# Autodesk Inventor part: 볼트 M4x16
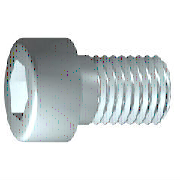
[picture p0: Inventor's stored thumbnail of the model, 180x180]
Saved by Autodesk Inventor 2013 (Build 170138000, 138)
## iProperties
IsCustomPart: 1
Created: 2012-02
Part Number: 볼트 M4x16
Material: 강철, 연강
Description: 6각머리 태핑 나사
Document SubType Name: Modeling
Standard: KS B 1003
Designer: mduedu
Standards Organization: KS
Language: ko-KR
Size Designation: M 4 x 16
Categories: <MemberInstance><Categories><Category DisplayName="조임쇠" InternalName="e4da775c-781d-43d5-af7c-5136215cf5a6" Mnemonic="FSTN"><Category DisplayName="볼트" InternalN
Density: 1 g/cm^3
Author: mduedu
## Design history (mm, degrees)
sketch "스케치1"
  geometry: L1 (-1, 0)-(16, 0); L2 (16, 0)-(16, 2); L3 (16, 2)-(1.75, 2); L4 (1.75, 2)-(1.32, 2); L5 (1.32, 2)-(0, 2); L6 (0, 2)-(0, 3.5); L7 (0, 3.5)-(-4, 3.5); L8 (-4, 3.5)-(-4, 1.732); L9 (-4, 1.732)-(-2, 1.732); L10 (-2, 1.732)-(-1, 0); L11 (-8, 0)-(20, 0) reference; L12 (0, -0.7)-(0, 4.2) reference; L13 (1.75, 2)-(0, 2)
  constraints: 22 end point, 6 parallel, 2 collinear, 2 perpendicular, 1 horizontal, 1 point on line
  dimensions: "d1" = 14.25 distance from line of L3.end L2 (= GEL); "d2" = 0.42952 distance of L4.end L3.end (computed from GAL); "d3" = 4 distance between parallel lines of L8 L6 (= KOH); "d4" = 2 distance of L8.end L9.end (= INTI); "d5" = 60 deg angle of L10 L1; "d6" = 4 diameter of L3 L1 (= GD); "d7" = 4 diameter of L5 L1 (= BDM); "d8" = 3.4641 diameter of L9 L1 (= 1.1547 x SW); "d9" = 7 diameter of L7 L1 (= KOD); "d26" = 16 distance between parallel lines of L12 L2 (= NLG)
revolve "본체" sketch "스케치1" stored, may be unused: angle "d10" = 90 deg
sketch "스케치2"
  geometry: L1 (0, -4.9)-(0, 4.9) reference; L2 (-4.9, 0)-(4.9, 0) reference; L3 (1.732, 0)-(0.866, -1.5); L4 (0.866, -1.5)-(-0.866, -1.5); L5 (-0.866, -1.5)-(-1.732, 0); L6 (-1.732, 0)-(-0.866, 1.5); L7 (-0.866, 1.5)-(0.866, 1.5); L8 (0.866, 1.5)-(1.732, 0); 2 further points
  constraints: 12 end point, 1 coincident, 1 horizontal alignment, 1 point on line, 12 other
extrude "슬롯" join sketch "스케치2" stored distance "d11" = 10; taper "d12" = 0 deg
workplane "Work Plane1"
fillet "Fillet2" dims "d30" = 0.1 (= R)
body "Solid1"
fillet "모깎기1" dims "d17" = 0.4 (= RR)
feature "스레드" dims "d13" = 14.25 (= GEL), "d14" = 0
chamfer "모따기1" distance "d15" = 0.42941 (= -0.5 x SPD + 0.5 x GD); stored, may be unused: second distance "d16" = 0.42941 (= GUL), angle "d27" = 45 deg
other parameters: "GD" = 4 (= NND) [user parameter; used in 2 equation terms], "NLG" = 16 [user parameter; used in 1 equation term], "GEL" = 14.25 [user parameter; used in 2 equation terms], "KOD" = 7 [user parameter; used in 1 equation term], "KOH" = 4 [user parameter; used in 1 equation term], "INTI" = 2 [user parameter; used in 1 equation term], "GAL" = 0.42941 (= 0.61345 x PTC) [user parameter; used in 1 equation term], "GUL" = 0.42941 (= 0.61345 x PTC) [user parameter; used in 1 equation term], "BDM" = 4 (= NND) [user parameter; used in 1 equation term], "SW" = 3 [user parameter; used in 2 equation terms], "RR" = 0.4 [user parameter; used in 1 equation term], "SPD" = 3.14117 (= NND - 1.2269 x PTC) [user parameter; used in 1 equation term], "d19" = 0, "d28" = 0, "d29" = 0, "R" = 0.1 [user parameter; used in 1 equation term], "PHH" = 0.2 [user parameter], "GD1" = 3.14117 (= THREADDIA - 1.2269 x PTC) [user parameter], "THREADDIA" = 4 [user parameter; used in 1 equation term], "FAWI" = 45 deg [user parameter], "TPU" = 14.28571 (computed from PTC) [user parameter], "PTC" = 0.7 [user parameter; used in 5 equation terms], "NND" = 4 [user parameter; used in 3 equation terms], "TOA" = 30 deg [user parameter], "E0" = 3.465 (= 1.155 x SW) [user parameter]
